// Mitsubishi GX Works2 project: MC-20MR-4MTS-F430-H3U-A   PLC: FX3G

PROGRAM MAIN
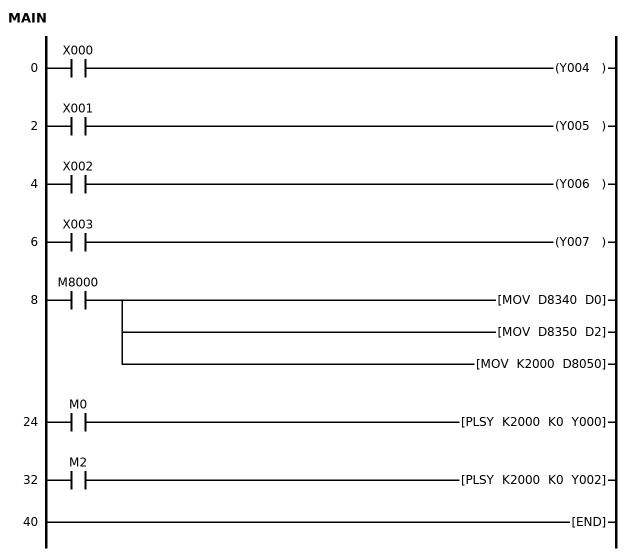
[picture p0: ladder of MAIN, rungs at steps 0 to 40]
0     LD      X000
      OUT     Y004
2     LD      X001
      OUT     Y005
4     LD      X002
      OUT     Y006
6     LD      X003
      OUT     Y007
8     LD      M8000
      MOV     D8340 D0
      MOV     D8350 D2
      MOV     K2000 D8050
24    LD      M0
      PLSY    K2000 K0 Y000
32    LD      M2
      PLSY    K2000 K0 Y002
40    END
END_PROGRAM
